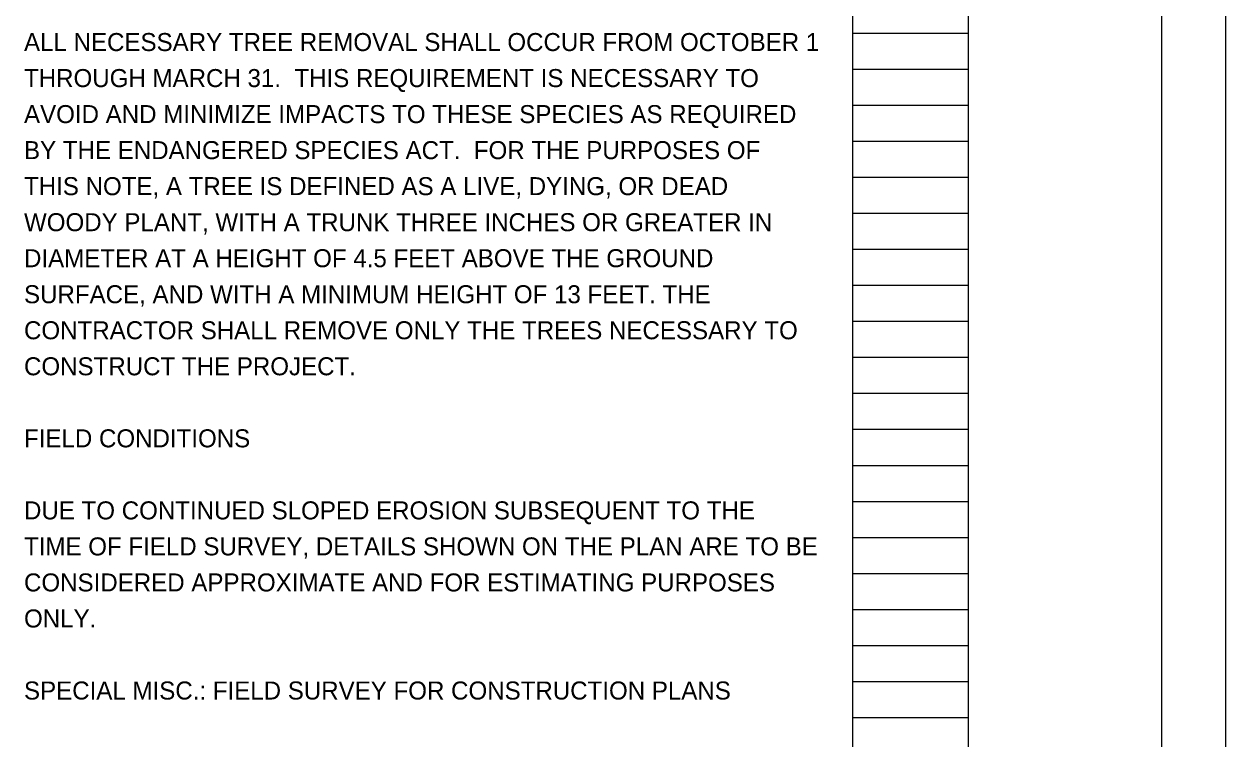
# Model space of a CAD drawing. Extents: x 0 to 58.9, y 0 to 22.
# Drawn here: x 24.66 to 34, y 5.57 to 11.13 of the extents above; entities that cross this region are included whole.
import ezdxf

# ---------------------------------------------------------------- set-up
doc = ezdxf.new("R2010")
doc.units = 0
for name, color, linetype in [('CS-ALGN-CNTR', 7, 'Continuous'), ('CS-ALGN-TEXT', 7, 'Continuous'), ('CS-ANNO-MATC', 7, 'Continuous'), ('CS-ANNO-MATC-MASK', 7, 'Continuous')]:
    doc.layers.add(name, color=color, linetype=linetype)

msp = doc.modelspace()

# ---------------------------------------------------------------- linework, layer by layer
at = {"layer": 'CS-ALGN-CNTR'}
msp.add_lwpolyline([(0, 0), (34, 0), (34, 22), (0, 22)], close=True, dxfattribs=at)
at = {"layer": 'CS-ALGN-TEXT'}
msp.add_line((32, 0.5), (32, 21.5), dxfattribs=at)
msp.add_lwpolyline([(1.5, 21.5), (33.5, 21.5), (33.5, 0.5), (1.5, 0.5)], close=True, dxfattribs=at)
at = {"layer": 'CS-ANNO-MATC-MASK'}
for p, q in [((31.1, 0.98), (31.1, 21.14)), ((32, 0.98), (32, 21.14)), ((31.1, 11.06), (32, 11.06)), ((31.1, 10.78), (32, 10.78)), ((31.1, 10.5), (32, 10.5)), ((31.1, 10.22), (32, 10.22)), ((31.1, 9.94), (32, 9.94)), ((31.1, 9.66), (32, 9.66)), ((31.1, 9.38), (32, 9.38)), ((31.1, 9.1), (32, 9.1)), ((31.1, 8.82), (32, 8.82)), ((31.1, 8.54), (32, 8.54)), ((31.1, 8.26), (32, 8.26)), ((31.1, 7.98), (32, 7.98)), ((31.1, 7.7), (32, 7.7)), ((31.1, 7.42), (32, 7.42)), ((31.1, 7.14), (32, 7.14)), ((31.1, 6.86), (32, 6.86)), ((31.1, 6.58), (32, 6.58)), ((31.1, 6.3), (32, 6.3)), ((31.1, 6.02), (32, 6.02)), ((31.1, 5.74), (32, 5.74))]:
    msp.add_line(p, q, dxfattribs=at)

# ---------------------------------------------------------------- texts
at = {"layer": 'CS-ANNO-MATC'}
for s, p in [('ALL NECESSARY TREE REMOVAL SHALL OCCUR FROM OCTOBER 1 ', (24.66, 10.92)), ('THROUGH MARCH 31.  THIS REQUIREMENT IS NECESSARY TO ', (24.66, 10.64)), ('AVOID AND MINIMIZE IMPACTS TO THESE SPECIES AS REQUIRED ', (24.66, 10.36)), ('BY THE ENDANGERED SPECIES ACT.  FOR THE PURPOSES OF ', (24.66, 10.08)), ('THIS NOTE, A TREE IS DEFINED AS A LIVE, DYING, OR DEAD ', (24.66, 9.8)), ('WOODY PLANT, WITH A TRUNK THREE INCHES OR GREATER IN ', (24.66, 9.52)), ('DIAMETER AT A HEIGHT OF 4.5 FEET ABOVE THE GROUND ', (24.66, 9.24)), ('SURFACE, AND WITH A MINIMUM HEIGHT OF 13 FEET. THE ', (24.66, 8.96)), ('CONTRACTOR SHALL REMOVE ONLY THE TREES NECESSARY TO ', (24.66, 8.68)), ('CONSTRUCT THE PROJECT.', (24.66, 8.4)), ('FIELD CONDITIONS', (24.66, 7.84)), ('DUE TO CONTINUED SLOPED EROSION SUBSEQUENT TO THE ', (24.66, 7.28)), ('TIME OF FIELD SURVEY, DETAILS SHOWN ON THE PLAN ARE TO BE ', (24.66, 7)), ('CONSIDERED APPROXIMATE AND FOR ESTIMATING PURPOSES ', (24.66, 6.72)), ('ONLY.', (24.66, 6.44)), ('SPECIAL MISC.: FIELD SURVEY FOR CONSTRUCTION PLANS ', (24.66, 5.88))]:
    msp.add_text(s, height=0.14, dxfattribs=at).set_placement(p)

doc.saveas('drawing.dxf')
